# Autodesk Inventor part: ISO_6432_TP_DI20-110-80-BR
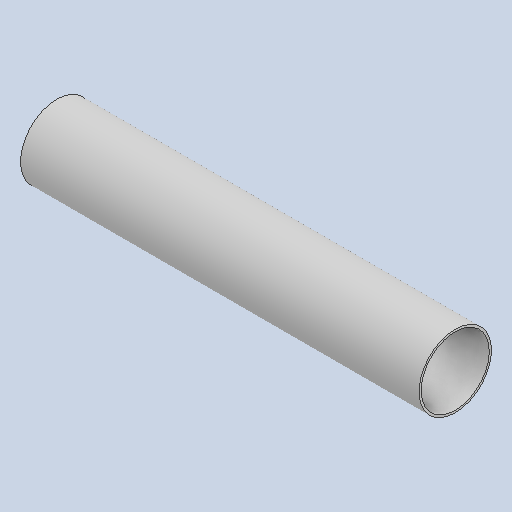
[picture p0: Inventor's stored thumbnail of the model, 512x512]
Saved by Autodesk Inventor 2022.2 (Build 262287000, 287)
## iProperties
Created: 2024-10
Part Number: ISO_6432_TP_DI20-110-80-BR
Material: Generico
Document SubType Name: Modeling
Designer: 18907419
Density: 1 g/cm^3
Appearance: Default
Author: 18907419
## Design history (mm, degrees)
feature "Solid1"
node "Solido1"
